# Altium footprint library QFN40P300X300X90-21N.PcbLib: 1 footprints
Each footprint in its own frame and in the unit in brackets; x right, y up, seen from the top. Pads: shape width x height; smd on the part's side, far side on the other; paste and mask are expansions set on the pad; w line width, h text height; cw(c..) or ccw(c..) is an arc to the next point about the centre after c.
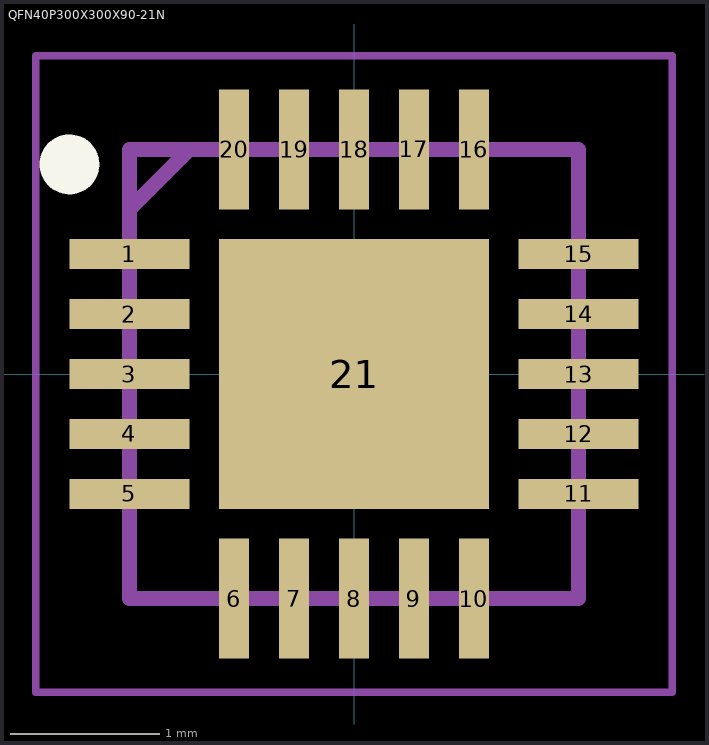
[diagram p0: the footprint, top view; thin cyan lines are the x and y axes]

## QFN40P300X300X90-21N [mm]
pads (21):
  rect 0.8x0.2 smd: 1(-1.5,0.8) 2(-1.5,0.4) 3(-1.5,0) 4(-1.5,-0.4) 5(-1.5,-0.8) 11(1.5,-0.8) 12(1.5,-0.4) 13(1.5,0) 14(1.5,0.4) 15(1.5,0.8)
  rect 0.2x0.8 smd: 6(-0.8,-1.5) 7(-0.4,-1.5) 8(0,-1.5) 9(0.4,-1.5) 10(0.8,-1.5) 16(0.8,1.5) 17(0.4,1.5) 18(0,1.5) 19(-0.4,1.5) 20(-0.8,1.5)
  rect 1.8x1.8 smd: 21(0,0)
Top Overlay:
  circle w0.2: c-1.9,1.4 r0.1
Mechanical 15:
  lines w0.1: -1.5,1.1 -1.1,1.5 ; -1.5,-1.5 1.5,-1.5 1.5,1.5 -1.5,1.5 -1.5,-1.5
Mechanical 20:
  lines w0.05: -2.125,-2.125 2.125,-2.125 2.125,2.125 -2.125,2.125 -2.125,-2.125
